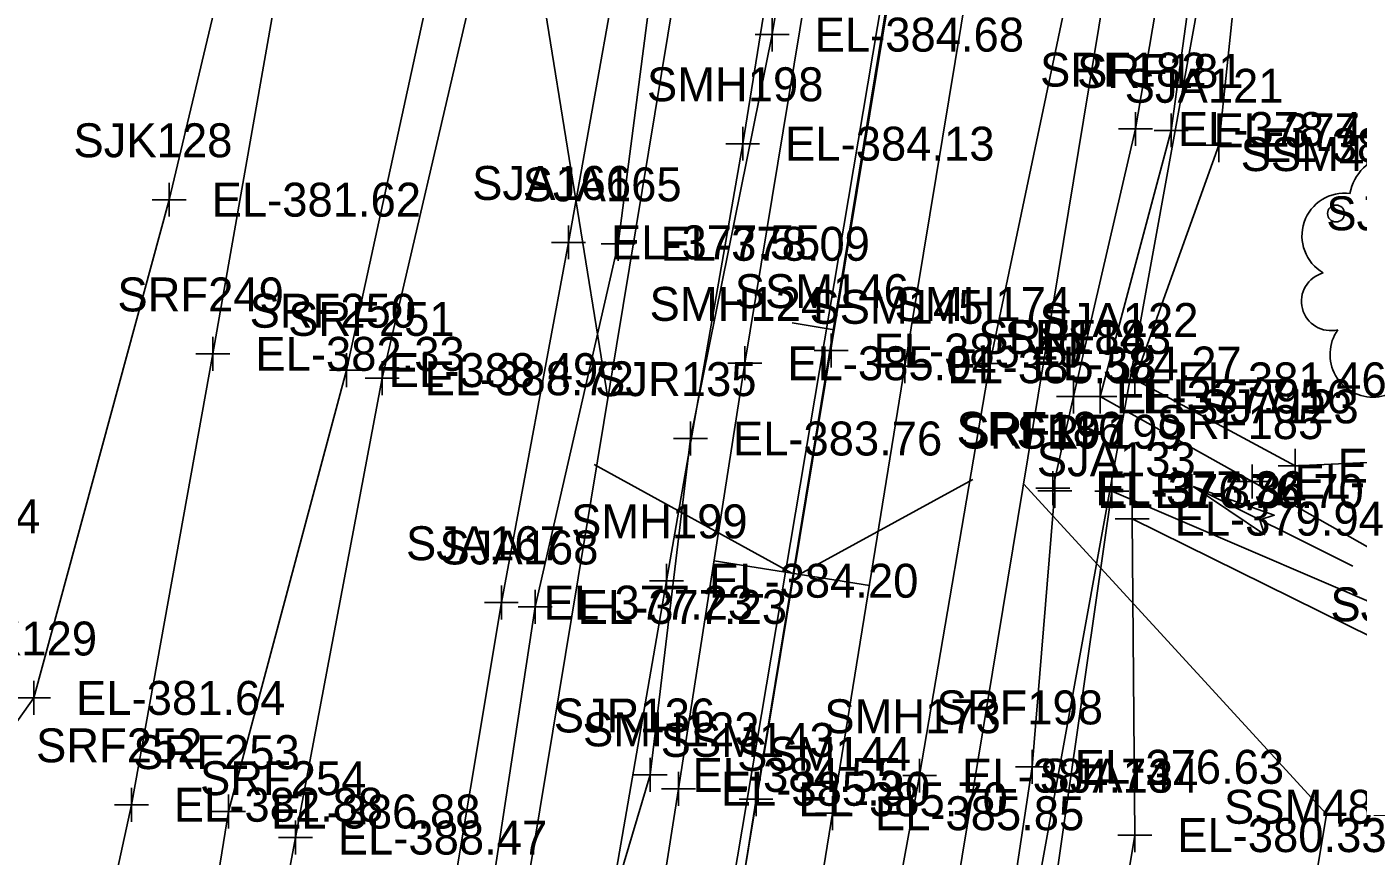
# Model space of a CAD drawing. Extents: x 1189978 to 1314812, y 571533 to 629339.
# Drawn here: x 1217522.9 to 1217679.8, y 621862.8 to 621960.6 of the extents above; entities that cross this region are included whole.
import ezdxf

# ---------------------------------------------------------------- set-up
doc = ezdxf.new("R2010")
doc.units = 0
for name, color, linetype in [('SURVEY - CENTERLINE - Preliminary', 7, 'Continuous'), ('SURVEY - CENTERLINE - Preliminary Text', 7, 'Continuous'), ('SURVEY - DRAINAGE - Area Shapes', 7, 'Continuous'), ('SURVEY - DRAINAGE - Bridge Hydraulic Data with Text', 7, 'Continuous'), ('SURVEY - DTM - Breaklines', 7, 'Continuous'), ('SURVEY - DTM - Breaklines - Points - Elevations', 7, 'Continuous'), ('SURVEY - DTM - Breaklines - Points - Locators', 7, 'Continuous'), ('SURVEY - DTM - Breaklines - Points - Numbers', 7, 'Continuous'), ('SURVEY - DTM - Spot Points - Elevations', 7, 'Continuous'), ('SURVEY - DTM - Spot Points - Locators', 7, 'Continuous'), ('SURVEY - DTM - Spot Points - Point Numbers', 7, 'Continuous'), ('SURVEY - PROPERTY - ROW Lines', 7, 'Continuous'), ('SURVEY - PROPERTY - ROW Lines Text', 7, 'Continuous'), ('SURVEY - TRANSPORTATION - Roads', 7, 'Continuous'), ('SURVEY - TRANSPORTATION - Roads - Points - Elevations', 7, 'Continuous'), ('SURVEY - TRANSPORTATION - Roads - Points - Locators', 7, 'Continuous'), ('SURVEY - TRANSPORTATION - Roads - Points - Numbers', 7, 'Continuous'), ('SURVEY - UTILITIES - Electric (Overhead) with Text', 7, 'Continuous'), ('SURVEY - UTILITIES - Poles and Miscellaneous - Points - Numbers', 7, 'Continuous'), ('SURVEY - VEGETATION - Features - Points - Elevations', 7, 'Continuous'), ('SURVEY - VEGETATION - Features - Points - Locators', 7, 'Continuous'), ('SURVEY - VEGETATION - Features - Points - Numbers', 7, 'Continuous'), ('SURVEY - VEGETATION - Features with Text', 7, 'Continuous')]:
    doc.layers.add(name, color=color, linetype=linetype)

msp = doc.modelspace()

# ---------------------------------------------------------------- linework, layer by layer
at = {"layer": 'SURVEY - CENTERLINE - Preliminary'}
msp.add_line((1217525.37, 621363.65), (1217649.69, 622116.55), dxfattribs=at)
msp.add_line((1217525.37, 621363.65), (1217649.69, 622116.55), dxfattribs=at)
at = {"layer": 'SURVEY - CENTERLINE - Preliminary Text'}
msp.add_line((1217618.04, 621924.86), (1217613.1, 621925.67), dxfattribs=at)
at = {"layer": 'SURVEY - DRAINAGE - Area Shapes'}
msp.add_line((1217415.87, 620731.68), (1218149.36, 625079.9), dxfattribs=at)
at = {"layer": 'SURVEY - DRAINAGE - Bridge Hydraulic Data with Text'}
msp.add_line((1217679.19, 621896.99), (1217660.39, 621906.37), dxfattribs=at)
msp.add_lwpolyline([(1217660.39, 621906.37), (1217669.94, 621903), (1217668.22, 621902.46), (1217668.8, 621900.72)], close=True, dxfattribs=at)
msp.add_lwpolyline([(1217660.39, 621906.37), (1217669.94, 621903), (1217668.22, 621902.46), (1217668.8, 621900.72), (1217660.39, 621906.37)], dxfattribs=at)
at = {"layer": 'SURVEY - DTM - Breaklines'}
for points in [[(1217591.74, 621765.73), (1217601.34, 621822.74), (1217608.84, 621869.52), (1217625.54, 621971.19), (1217634.6, 622026.63), (1217643.17, 622076.74), (1217651.21, 622124.47), (1217659.56, 622173.57), (1217668.17, 622224.78), (1217678.08, 622282.54), (1217688.16, 622340.37), (1217697.26, 622392.62), (1217705.46, 622440.01), (1217714.49, 622490.86), (1217723.28, 622541.33), (1217731.44, 622588.51), (1217739.96, 622637.78), (1217748.52, 622688.04), (1217748.57, 622688.21), (1217756.95, 622738.51)], [(1217685.05, 622529.18), (1217678.55, 622499.44), (1217670.66, 622464.16), (1217662, 622418.29), (1217653.65, 622375.31), (1217647.46, 622326.5), (1217637.7, 622278.06), (1217624.97, 622233.51), (1217617.77, 622187.81), (1217609.29, 622147.05), (1217599.66, 622101.36), (1217592.56, 622056.45), (1217583.44, 622007.19), (1217575.28, 621964.22), (1217564.77, 621919.14), (1217554.54, 621865.01), (1217546.46, 621821.67), (1217537.02, 621781.08), (1217528.09, 621784.53), (1217517.71, 621784.08)], [(1217681.03, 622529.83), (1217673.16, 622499.61), (1217666.36, 622465.44), (1217655.82, 622419.52), (1217648.28, 622375.91), (1217643.04, 622327.33), (1217632.09, 622280.16), (1217619.71, 622235.27), (1217613.14, 622189.16), (1217602.51, 622145.75), (1217593.94, 622101.94), (1217587.9, 622057.35), (1217577.79, 622010.33), (1217570.45, 621965.56), (1217560.55, 621920.1), (1217546.67, 621868.08), (1217539.32, 621822.52), (1217534.84, 621801.11)], [(1217668.55, 622519.09), (1217665.88, 622505.91), (1217655.91, 622467.59), (1217646.62, 622422.12), (1217637.66, 622376.33), (1217630.45, 622330.1), (1217619.94, 622285.29), (1217610.06, 622239.5), (1217600.78, 622197.96), (1217592.86, 622149.6), (1217580.28, 622104.6), (1217573.51, 622060.94), (1217562.45, 622014.24), (1217553.23, 621969.79), (1217544.82, 621922.02), (1217535.21, 621868.88), (1217526.29, 621827.9)], [(1217696.43, 622511.42), (1217690.45, 622501.14), (1217682.75, 622461.47), (1217672.56, 622421.42), (1217668.77, 622381.8), (1217659.15, 622328.76), (1217653.09, 622287.28), (1217639.42, 622228.14), (1217631.31, 622175.39), (1217620.6, 622119.17), (1217610.69, 622074.17), (1217604.05, 622032.34), (1217595.02, 621981.54), (1217586.73, 621935.16), (1217578.82, 621892.7), (1217571.48, 621848.7), (1217561.74, 621801.1), (1217546.07, 621743.68), (1217517.89, 621741.61)], [(1217697.46, 622510.95), (1217695.23, 622500.63), (1217687.54, 622460.4), (1217680.36, 622419.79), (1217673.4, 622382.01), (1217663.19, 622329.29), (1217655.83, 622286.39), (1217645.17, 622227.36), (1217637.36, 622175.23), (1217627.75, 622118.91), (1217619.76, 622071.57), (1217612.88, 622029.47), (1217598.58, 621981.08), (1217592.58, 621934.99), (1217582.82, 621892.2), (1217576.26, 621849.18), (1217566.85, 621799.58), (1217549.42, 621742.26), (1217567.14, 621728.67)], [(1217704.42, 622509.33), (1217700.3, 622496.16), (1217691.81, 622446.34), (1217683.59, 622396.11), (1217675.05, 622345.79), (1217666.22, 622294.23), (1217657.54, 622241.9), (1217648.88, 622192.24), (1217640.73, 622142.53), (1217632.56, 622094.35), (1217625.38, 622048.54), (1217615.19, 621995.99), (1217607.27, 621946.79), (1217598.3, 621895.28), (1217589.38, 621843.86), (1217580.22, 621794.45), (1217573.72, 621781.31), (1217574.43, 621774.4), (1217580.6, 621768.52)], [(1217604.56, 621765.51), (1217608.59, 621775.31), (1217618.98, 621822.73), (1217628.13, 621872.31), (1217636.41, 621920.88), (1217646.75, 621970.08), (1217652.31, 622022.79), (1217663.53, 622069.73), (1217672.49, 622118.54), (1217678.26, 622168.97), (1217683.24, 622219.55), (1217691.94, 622272.25), (1217701.2, 622320.93), (1217709.61, 622368.48), (1217718.57, 622415.45), (1217724.25, 622459.08), (1217730.45, 622491.37), (1217730.86, 622507.08)], [(1217734.86, 622491.68), (1217727.91, 622445.78), (1217720.64, 622398.43), (1217714.5, 622352.23), (1217706.13, 622302.11), (1217699.65, 622260.42), (1217693, 622212.18), (1217687.82, 622174.51), (1217684.08, 622136.25), (1217675.85, 622096.46), (1217671.96, 622067.67), (1217669.46, 622048.53), (1217661.22, 621993.63), (1217653.56, 621948.52), (1217646.28, 621917), (1217643.83, 621906.18), (1217644.06, 621905.86), (1217641.41, 621873.35), (1217633.96, 621824.29), (1217625.6, 621785.71), (1217619.08, 621762.41), (1217607.58, 621724.78)], [(1217697.47, 622046.01), (1217672.43, 622047.59), (1217663.85, 621992.57), (1217657.77, 621948.36), (1217649.39, 621917), (1217667.32, 621906.97), (1217691.53, 621893.28), (1217727.19, 621910.94), (1217768.29, 621913.65), (1217812.92, 621906.99)], [(1217688.16, 622042.74), (1217674.29, 622044.09), (1217668.19, 621992.33), (1217663.38, 621946.61), (1217653.5, 621919.01), (1217672.39, 621908.83), (1217708.13, 621910.46), (1217733.66, 621916.96), (1217767.69, 621917.46), (1217813.77, 621911.49)], [(1217811.7, 621901.16), (1217779.34, 621909.31), (1217747.54, 621909.93), (1217718.08, 621904.38), (1217691.05, 621888.56), (1217650.79, 621905.84), (1217638.96, 621823.55), (1217629.18, 621784.22), (1217617.29, 621724.56)], [(1217807.62, 621897.63), (1217776.71, 621903.65), (1217742.67, 621903.28), (1217721.64, 621897.05), (1217687.78, 621885.5), (1217653.18, 621902.59), (1217653.49, 621865.3), (1217645.85, 621819.19), (1217636.03, 621782.93), (1217634.51, 621740.79)]]:
    msp.add_lwpolyline(points, dxfattribs=at)
at = {"layer": 'SURVEY - DTM - Breaklines - Points - Locators'}
for p, q in [((1217653.56, 621950.52), (1217653.56, 621946.52)), ((1217657.77, 621950.36), (1217657.77, 621946.36)), ((1217607.27, 621948.79), (1217607.27, 621944.79)), ((1217655.56, 621948.52), (1217651.56, 621948.52)), ((1217659.77, 621948.36), (1217655.77, 621948.36)), ((1217663.38, 621948.61), (1217663.38, 621944.61)), ((1217609.27, 621946.79), (1217605.27, 621946.79)), ((1217665.38, 621946.61), (1217661.38, 621946.61)), ((1217586.73, 621937.16), (1217586.73, 621933.16)), ((1217592.58, 621936.99), (1217592.58, 621932.99)), ((1217588.73, 621935.16), (1217584.73, 621935.16)), ((1217594.58, 621934.99), (1217590.58, 621934.99)), ((1217617.69, 621924.41), (1217617.69, 621920.41)), ((1217544.82, 621924.02), (1217544.82, 621920.02)), ((1217636.41, 621922.88), (1217636.41, 621918.88)), ((1217546.82, 621922.02), (1217542.82, 621922.02)), ((1217560.55, 621922.1), (1217560.55, 621918.1)), ((1217564.77, 621921.14), (1217564.77, 621917.14)), ((1217619.69, 621922.41), (1217615.69, 621922.41)), ((1217653.5, 621921.01), (1217653.5, 621917.01)), ((1217562.55, 621920.1), (1217558.55, 621920.1)), ((1217638.41, 621920.88), (1217634.41, 621920.88)), ((1217566.77, 621919.14), (1217562.77, 621919.14)), ((1217646.28, 621919), (1217646.28, 621915)), ((1217649.39, 621919), (1217649.39, 621915)), ((1217655.5, 621919.01), (1217651.5, 621919.01)), ((1217648.28, 621917), (1217644.28, 621917)), ((1217651.39, 621917), (1217647.39, 621917)), ((1217672.39, 621910.83), (1217672.39, 621906.83)), ((1217667.32, 621908.97), (1217667.32, 621904.97)), ((1217674.39, 621908.83), (1217670.39, 621908.83)), ((1217643.83, 621908.18), (1217643.83, 621904.18)), ((1217644.06, 621907.86), (1217644.06, 621903.86)), ((1217650.79, 621907.84), (1217650.79, 621903.84)), ((1217669.32, 621906.97), (1217665.32, 621906.97)), ((1217645.83, 621906.18), (1217641.83, 621906.18)), ((1217646.06, 621905.86), (1217642.06, 621905.86)), ((1217652.79, 621905.84), (1217648.79, 621905.84)), ((1217653.18, 621904.59), (1217653.18, 621900.59)), ((1217655.18, 621902.59), (1217651.18, 621902.59)), ((1217598.3, 621897.28), (1217598.3, 621893.28)), ((1217578.82, 621894.7), (1217578.82, 621890.7)), ((1217600.3, 621895.28), (1217596.3, 621895.28)), ((1217580.82, 621892.7), (1217576.82, 621892.7)), ((1217582.82, 621894.2), (1217582.82, 621890.2)), ((1217584.82, 621892.2), (1217580.82, 621892.2)), ((1217628.13, 621874.31), (1217628.13, 621870.31)), ((1217641.41, 621875.35), (1217641.41, 621871.35)), ((1217630.13, 621872.31), (1217626.13, 621872.31)), ((1217643.41, 621873.35), (1217639.41, 621873.35)), ((1217535.21, 621870.88), (1217535.21, 621866.88)), ((1217608.84, 621871.52), (1217608.84, 621867.52)), ((1217546.67, 621870.08), (1217546.67, 621866.08)), ((1217610.84, 621869.52), (1217606.84, 621869.52)), ((1217537.21, 621868.88), (1217533.21, 621868.88)), ((1217548.67, 621868.08), (1217544.67, 621868.08)), ((1217554.54, 621867.01), (1217554.54, 621863.01)), ((1217653.49, 621867.3), (1217653.49, 621863.3)), ((1217556.54, 621865.01), (1217552.54, 621865.01)), ((1217655.49, 621865.3), (1217651.49, 621865.3))]:
    msp.add_line(p, q, dxfattribs=at)
at = {"layer": 'SURVEY - DTM - Spot Points - Locators'}
msp.add_circle((1217677.21, 621938.56), 1, dxfattribs=at)
at = {"layer": 'SURVEY - PROPERTY - ROW Lines'}
for p, q in [((1217557.72, 621713), (1217625.03, 622120.62)), ((1217606.4, 621700.95), (1217674.36, 622112.48))]:
    msp.add_line(p, q, dxfattribs=at)
at = {"layer": 'SURVEY - PROPERTY - ROW Lines Text'}
msp.add_line((1217676.08, 621867.78), (1217665.06, 621801.03), dxfattribs=at)
for points in [[(1217583.45, 621966.01), (1217591.37, 621916.81)], [(1217676.08, 621867.78), (1217640.38, 621906.71)]]:
    msp.add_lwpolyline(points, dxfattribs=at)
at = {"layer": 'SURVEY - TRANSPORTATION - Roads'}
for points in [[(1217582.48, 621767.23), (1217583.27, 621767.61), (1217591.48, 621818.57), (1217599.69, 621870.76), (1217607.53, 621920.91), (1217615.95, 621971.91), (1217624.34, 622024.82), (1217633.57, 622076.49), (1217641.88, 622125.54), (1217650.64, 622175.68), (1217659.24, 622225.33), (1217669.03, 622282.56), (1217679.25, 622341.35), (1217687.87, 622391.11), (1217696.47, 622441.53), (1217705.33, 622491.37), (1217713.95, 622541.79), (1217722.13, 622587.98), (1217731.03, 622638.52), (1217739.75, 622690.1), (1217739.95, 622691.24)], [(1217602.44, 621764.03), (1217601.61, 621764.4), (1217609.73, 621817.52), (1217617.85, 621867.88), (1217626.38, 621920.56), (1217634.53, 621969.83), (1217643.58, 622024.64), (1217652.44, 622075.54), (1217660.7, 622123.44), (1217668.82, 622172.59), (1217677.49, 622224.09), (1217697.4, 622338.83), (1217706.31, 622389.43), (1217714.67, 622438.11), (1217723.73, 622488.94), (1217732.47, 622539.47), (1217740.61, 622586), (1217749.34, 622636.23), (1217757.51, 622686.56)]]:
    msp.add_lwpolyline(points, dxfattribs=at)
at = {"layer": 'SURVEY - TRANSPORTATION - Roads - Points - Locators'}
for p, q in [((1217607.53, 621922.91), (1217607.53, 621918.91)), ((1217626.38, 621922.56), (1217626.38, 621918.56)), ((1217609.53, 621920.91), (1217605.53, 621920.91)), ((1217628.38, 621920.56), (1217624.38, 621920.56)), ((1217599.69, 621872.76), (1217599.69, 621868.76)), ((1217601.69, 621870.76), (1217597.69, 621870.76)), ((1217617.85, 621869.88), (1217617.85, 621865.88)), ((1217619.85, 621867.88), (1217615.85, 621867.88))]:
    msp.add_line(p, q, dxfattribs=at)
at = {"layer": 'SURVEY - UTILITIES - Electric (Overhead) with Text'}
msp.add_lwpolyline([(1217806.14, 622777), (1217743.09, 622422.64), (1217688.2, 622113.29), (1217626.83, 621775.19), (1217569.14, 621442.23), (1217508.83, 621100.02), (1217448.24, 620751.9)], dxfattribs=at)
at = {"layer": 'SURVEY - UTILITIES - Poles and Miscellaneous - Points - Numbers'}
for p, q in [((1217613.06, 621896.17), (1217589.75, 621908.97)), ((1217613.91, 621896.03), (1217634.4, 621907.2)), ((1217603.92, 621897.61), (1217622.2, 621894.73))]:
    msp.add_line(p, q, dxfattribs=at)
at = {"layer": 'SURVEY - VEGETATION - Features - Points - Locators'}
for p, q in [((1217610.75, 621961.64), (1217610.75, 621957.64)), ((1217612.75, 621959.64), (1217608.75, 621959.64)), ((1217539.67, 621942.19), (1217539.67, 621938.19)), ((1217541.67, 621940.19), (1217537.67, 621940.19)), ((1217601.11, 621914.04), (1217601.11, 621910.04)), ((1217603.11, 621912.04), (1217599.11, 621912.04)), ((1217523.69, 621883.47), (1217523.69, 621879.47)), ((1217525.69, 621881.47), (1217521.69, 621881.47)), ((1217596.35, 621874.4), (1217596.35, 621870.4)), ((1217598.35, 621872.4), (1217594.35, 621872.4))]:
    msp.add_line(p, q, dxfattribs=at)
at = {"layer": 'SURVEY - VEGETATION - Features with Text'}
for points in [[(1217575.08, 621774.11), (1217450.26, 621814.85), (1217450.11, 621824.86), (1217507.38, 621858.46), (1217523.69, 621881.47), (1217539.67, 621940.19), (1217555.11, 622005.06), (1217569.39, 622072.91), (1217588.39, 622140.3), (1217598.23, 622184.22), (1217608.56, 622234.27), (1217619.43, 622285.83), (1217630.65, 622335.58), (1217641.81, 622391.46), (1217652.67, 622449.04), (1217659.71, 622500.99), (1217665.15, 622519.94)], [(1217702.96, 622509.49), (1217699.51, 622493.95), (1217693.48, 622453.44), (1217687.22, 622414.99), (1217679.9, 622375.82), (1217673.76, 622340.63), (1217665.91, 622295.21), (1217658.91, 622253.42), (1217654.9, 622206.36), (1217645.64, 622163.87), (1217637.41, 622119.23), (1217630.2, 622079.47), (1217625.49, 622037.7), (1217617.96, 622003.15), (1217610.75, 621959.64), (1217601.11, 621912.04), (1217596.35, 621872.4), (1217583.12, 621827.95), (1217575.08, 621774.11)]]:
    msp.add_lwpolyline(points, dxfattribs=at)
for centre, radius, start, end in [((1217684.51, 621939.88), 5.75, 31.9683, 169.4925), ((1217678.25, 621935.92), 5.05, 82.9155, 239.7044), ((1217676.6, 621928.21), 3.46, 105.0317, 283.7773), ((1217681.55, 621921.96), 5.04, 145.0523, 338.472)]:
    msp.add_arc(centre, radius, start, end, dxfattribs=at)

# ---------------------------------------------------------------- texts
at = {"layer": 'SURVEY - DTM - Breaklines - Points - Elevations'}
for s, p in [('EL-378.44', (1217658.56, 621946.52)), ('EL-377.91', (1217662.77, 621946.36)), ('EL-384.13', (1217612.27, 621944.79)), ('EL-381.66', (1217668.38, 621944.61)), ('EL-377.55', (1217591.73, 621933.16)), ('EL-378.09', (1217597.58, 621932.99)), ('EL-382.33', (1217549.82, 621920.02)), ('EL-385.49', (1217622.69, 621920.41)), ('EL-384.27', (1217641.41, 621918.88)), ('EL-388.49', (1217565.55, 621918.1)), ('EL-388.72', (1217569.77, 621917.14)), ('EL-381.46', (1217658.5, 621917.01)), ('EL-377.95', (1217651.28, 621915)), ('EL-377.16', (1217654.39, 621915)), ('EL-379.71', (1217677.39, 621906.83)), ('EL-376.75', (1217672.32, 621904.97)), ('EL-377.36', (1217648.83, 621904.18)), ('EL-376.84', (1217649.06, 621903.86)), ('EL-376.70', (1217655.79, 621903.84)), ('EL-379.94', (1217658.18, 621900.59)), ('EL-384.20', (1217603.3, 621893.28)), ('EL-377.23', (1217583.82, 621890.7)), ('EL-377.23', (1217587.82, 621890.2)), ('EL-376.63', (1217646.41, 621871.35)), ('EL-384.74', (1217633.13, 621870.31)), ('EL-382.88', (1217540.21, 621866.88)), ('EL-385.70', (1217613.84, 621867.52)), ('EL-386.88', (1217551.67, 621866.08)), ('EL-388.47', (1217559.54, 621863.01)), ('EL-380.33', (1217658.49, 621863.3))]:
    msp.add_text(s, height=4, dxfattribs=at).set_placement(p)
at = {"layer": 'SURVEY - DTM - Breaklines - Points - Numbers'}
for s, p in [('SRF182', (1217642.32, 621953.52)), ('SRF181', (1217646.69, 621953.36)), ('SMH198', (1217595.98, 621951.79)), ('SJA121', (1217652.29, 621951.61)), ('SJA166', (1217575.38, 621940.16)), ('SJA165', (1217581.34, 621939.99)), ('SRF249', (1217533.56, 621927.02)), ('SSM146', (1217606.34, 621927.41)), ('SRF250', (1217549.14, 621925.1)), ('SMH174', (1217625.17, 621925.88)), ('SRF251', (1217553.69, 621924.14)), ('SJA122', (1217642.26, 621924.01)), ('SRF184', (1217635.04, 621922)), ('SRF183', (1217638.15, 621922)), ('SJA123', (1217661.15, 621913.83)), ('SRF186', (1217632.48, 621911.18)), ('SRF197', (1217632.83, 621910.86)), ('SRF199', (1217639.53, 621910.84)), ('SRF185', (1217656.08, 621911.97)), ('SJA133', (1217641.94, 621907.59)), ('SMH199', (1217587.04, 621900.28)), ('SJA167', (1217567.58, 621897.7)), ('SJA168', (1217571.53, 621897.2)), ('SJA132', (1217676.55, 621890.5)), ('SRF198', (1217630.12, 621878.35)), ('SMH173', (1217616.89, 621877.31)), ('SSM143', (1217597.6, 621874.52)), ('SRF252', (1217523.97, 621873.88)), ('SRF253', (1217535.43, 621873.08)), ('SRF254', (1217543.3, 621870.01)), ('SJA134', (1217642.25, 621870.3))]:
    msp.add_text(s, height=4, dxfattribs=at).set_placement(p)
at = {"layer": 'SURVEY - DTM - Spot Points - Elevations'}
msp.add_text('EL-381.44', height=4, dxfattribs=at).set_placement((1217499.8, 621900.86))
at = {"layer": 'SURVEY - DTM - Spot Points - Point Numbers'}
for s, p in [('SSM483', (1217665.97, 621943.56)), ('SSM484', (1217664, 621866.64))]:
    msp.add_text(s, height=4, dxfattribs=at).set_placement(p)
at = {"layer": 'SURVEY - TRANSPORTATION - Roads - Points - Elevations'}
for s, p in [('EL-385.04', (1217612.53, 621918.91)), ('EL-385.58', (1217631.38, 621918.56)), ('EL-385.30', (1217604.69, 621868.76)), ('EL-385.85', (1217622.85, 621865.88))]:
    msp.add_text(s, height=4, dxfattribs=at).set_placement(p)
at = {"layer": 'SURVEY - TRANSPORTATION - Roads - Points - Numbers'}
for s, p in [('SMH124', (1217596.29, 621925.91)), ('SSM145', (1217615.14, 621925.56)), ('SMH123', (1217588.45, 621875.76)), ('SSM144', (1217606.61, 621872.88))]:
    msp.add_text(s, height=4, dxfattribs=at).set_placement(p)
at = {"layer": 'SURVEY - VEGETATION - Features - Points - Elevations'}
for s, p in [('EL-384.68', (1217615.75, 621957.64)), ('EL-381.62', (1217544.67, 621938.19)), ('EL-383.76', (1217606.11, 621910.04)), ('EL-381.64', (1217528.69, 621879.47)), ('EL-384.55', (1217601.35, 621870.4))]:
    msp.add_text(s, height=4, dxfattribs=at).set_placement(p)
at = {"layer": 'SURVEY - VEGETATION - Features - Points - Numbers'}
for s, p in [('SJK128', (1217528.38, 621945.19)), ('SJA241', (1217676.07, 621936.58)), ('SJR135', (1217589.87, 621917.04)), ('SJK129', (1217512.43, 621886.47)), ('SJR136', (1217585, 621877.4))]:
    msp.add_text(s, height=4, dxfattribs=at).set_placement(p)

doc.saveas('drawing.dxf')
